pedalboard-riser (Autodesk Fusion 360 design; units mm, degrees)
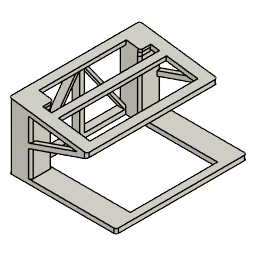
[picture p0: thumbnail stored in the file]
sketch "Sketch1" plane through (0, 0, 0) normal (0, 0, 1) x axis (1, 0, 0)
  line L1 (140.375, 0) -> (0, 0)
  line L2 (140.375, 171.375) -> (140.375, 0)
  line L3 (0, 171.375) -> (140.375, 171.375)
  line L4 (0, 0) -> (0, 171.375)
  point P1 (0, 0)
  point P2 (0, 0)
  point P3 (140.375, 0)
  point P5 (0, 171.375)
  horizontal L1
  vertical L2
  horizontal L3
  vertical L4
  coincident P1 P2
  dimension "d1" distance P2 P3 = 140.375
  dimension "d2" distance P2 P5 = 171.375
extrude "Extrude1" new body sketch "Sketch1" along normal blind 6.15
sketch "Sketch2" plane through (0, 0, 6.15) normal (0, 0, 1) x axis (-1, 0, 0)
  line L1 (0, 0) -> (0, -171.375)
  line L2 (-140.375, 0) -> (0, 0)
  line L3 (-140.375, -171.375) -> (-140.375, 0)
  line L4 (0, -171.375) -> (-140.375, -171.375)
  line L5 (-10, -28.549) -> (-130.375, -28.549)
  line L6 (-10, -142.826) -> (-10, -28.549)
  line L7 (-130.375, -142.826) -> (-10, -142.826)
  line L8 (-130.375, -28.549) -> (-130.375, -142.826)
  line L9 (-10, -85.6875) -> (0, -85.6875)
  line L10 (-130.375, -85.6875) -> (-140.375, -85.6875)
  line L11 (-70.1875, -28.549) -> (-70.1875, 0)
  line L12 (-70.1875, -142.826) -> (-70.1875, -171.375)
  point P10 (0, -85.6875)
  point P11 (-10, -85.6875)
  point P12 (-140.375, -85.6875)
  point P13 (-130.375, -85.6875)
  point P14 (-70.1875, 0)
  point P15 (-70.1875, -28.549)
  point P16 (-70.1875, -171.375)
  point P17 (-70.1875, -142.826)
  horizontal L5
  vertical L6
  horizontal L7
  vertical L8
  midpoint L1 P10
  coincident L6 P11
  perpendicular L6 L9
  midpoint L3 P12
  coincident L8 P13
  perpendicular L8 L10
  equal L9 L10
  midpoint L2 P14
  midpoint L5 P15
  midpoint L4 P16
  midpoint L7 P17
  equal L11 L12
  dimension "d5" distance L2 L5 = 28.549
  dimension "d7" distance L1 L6 = 10
extrude "Extrude2" cut sketch "Sketch2" profile of L5 L6 L7 L8 against normal blind 45
sketch "Sketch3" plane through (0, 0, 6.15) normal (0, 0, 1) x axis (-1, 0, 0)
  line L1 (-10, -142.826) -> (-10, -28.549)
  line L2 (-130.375, -142.826) -> (-10, -142.826)
  line L3 (-130.375, -28.549) -> (-130.375, -142.826)
  line L4 (-10, -28.549) -> (-130.375, -28.549)
  line L5 (0, 0) -> (0, -171.375)
  line L6 (-140.375, 0) -> (0, 0)
  line L7 (-140.375, -171.375) -> (-140.375, 0)
  line L8 (0, -171.375) -> (-140.375, -171.375)
  line L9 (-28.549, 0) -> (0, 0)
  line L10 (-28.549, -28.549) -> (-28.549, 0)
  line L11 (0, -28.549) -> (-28.549, -28.549)
  line L12 (0, 0) -> (0, -28.549)
  line L13 (-140.375, -85.6875) -> (0, -85.6875)
  line L14 (-140.375, -85.6875) -> (0, -85.6875)
  line L15 (0, -142.826) -> (-28.549, -142.826)
  line L16 (0, -171.375) -> (0, -142.826)
  line L17 (-28.549, -171.375) -> (0, -171.375)
  line L18 (-28.549, -142.826) -> (-28.549, -171.375)
  line L19 (-10, -28.549) -> (0, -28.549)
  point P12 (-28.549, -28.549)
  point P1 (0, 0)
  point P10 (0, 0)
  point P14 (0, -85.6875)
  point P15 (-140.375, -85.6875)
  point P20 (0, -171.375)
  point P11 (-28.549, 0)
  point P21 (-28.549, -171.375)
  point P18 (-28.549, -142.826)
  point P13 (0, -28.549)
  point P19 (0, -142.826)
  point P16 (0, -85.6875)
  point P17 (-140.375, -85.6875)
  horizontal L9
  vertical L10
  horizontal L11
  vertical L12
  coincident L4 P12
  coincident P1 P10
  midpoint L5 P14
  midpoint L7 P15
  symmetric P10 L13 P20
  symmetric P11 L13 P21
  symmetric P12 L13 P18
  symmetric P13 L13 P19
  symmetric P14 L13 P16
  symmetric P15 L13 P17
  horizontal L19
  equal L11 L12
extrude "Extrude3" add sketch "Sketch3" profile of L2 L4 L5 L6 L8 L9 L10 L11 L12 L15 L16 L17 L18 L19 along normal blind 80.4
sketch "Sketch4" plane through (0, 0, 0) normal (-1, 0, 0) x axis (0, -1, 0)
  line L1 (0, 0) -> (-171.375, 0)
  line L2 (0, 86.55) -> (0, 0)
  line L3 (-28.549, 86.55) -> (0, 86.55)
  line L4 (-28.549, 6.15) -> (-28.549, 86.55)
  line L5 (-142.826, 6.15) -> (-28.549, 6.15)
  line L6 (-142.826, 86.55) -> (-142.826, 6.15)
  line L7 (-171.375, 86.55) -> (-142.826, 86.55)
  line L8 (-171.375, 0) -> (-171.375, 86.55)
  line L9 (-85.6875, 6.15) -> (-85.6875, 0)
  line L10 (0, 86.55) -> (-171.375, 86.55)
  line L11 (0, 80.4) -> (0, 86.55)
  line L12 (-171.375, 80.4) -> (0, 80.4)
  line L13 (-171.375, 86.55) -> (-171.375, 80.4)
  line L14 (-85.6875, 86.55) -> (-85.6875, 0)
  line L15 (-82.6125, 86.55) -> (-88.7625, 86.55)
  line L16 (-82.6125, 0) -> (-82.6125, 86.55)
  line L17 (-88.7625, 0) -> (-82.6125, 0)
  line L18 (-88.7625, 86.55) -> (-88.7625, 0)
  line L19 (-88.7625, 43.275) -> (-85.6875, 43.275)
  line L20 (-82.6125, 43.275) -> (-85.6875, 43.275)
  line L21 (-142.826, 6.15) -> (-85.6875, 86.55)
  line L22 (-28.549, 6.15) -> (-85.6875, 86.55)
  line L23 (-88.7625, 86.55) -> (-142.826, 10.4769)
  line L24 (-28.549, 10.4769) -> (-82.6125, 86.55)
  line L25 (-88.7625, 80.4) -> (-141.5303, 6.15)
  line L26 (-29.8447, 6.15) -> (-82.6125, 80.4)
  line L27 (-88.7625, 86.55) -> (-88.7625, 80.4)
  line L28 (-82.6125, 86.55) -> (-82.6125, 80.4)
  point P10 (-85.6875, 0)
  point P11 (-85.6875, 6.15)
  point P14 (0, 80.4)
  point P9 (-171.375, 86.55)
  point P12 (-171.375, 86.55)
  point P16 (-85.6875, 86.55)
  point P19 (-82.6125, 0)
  point P17 (-88.7625, 86.55)
  point P21 (-85.6875, 43.275)
  point P22 (-88.7625, 43.275)
  point P23 (-82.6125, 43.275)
  point P7 (-142.826, 6.15)
  point P24 (-142.826, 6.15)
  point P6 (-28.549, 6.15)
  point P25 (-28.549, 6.15)
  point P26 (-142.826, 10.4769)
  point P27 (-28.549, 10.4769)
  point P28 (-141.5303, 6.15)
  point P29 (-88.7625, 80.4)
  point P30 (-82.6125, 80.4)
  point P31 (-29.8447, 6.15)
  midpoint L1 P10
  midpoint L5 P11
  horizontal L10
  vertical L11
  horizontal L12
  vertical L13
  coincident L2 P14
  coincident P9 P12
  equal L9 L13
  midpoint L10 P16
  horizontal L15
  vertical L16
  horizontal L17
  vertical L18
  coincident L1 P19
  coincident L10 P17
  equal L9 L15
  midpoint L14 P21
  midpoint L18 P22
  midpoint L16 P23
  equal L19 L20
  coincident P7 P24
  coincident P6 P25
  coincident L6 P26
  coincident L4 P27
  coincident L5 P28
  coincident L12 P29
  coincident L18 P29
  coincident L16 P30
  coincident L12 P30
  coincident L5 P31
  parallel L21 L23
  parallel L21 L25
  parallel L22 L26
  parallel L22 L24
extrude "Extrude4" add sketch "Sketch4" profile of L4 L5 L6 L10 L12 L15 L16 L18 L23 L24 L25 L26 L27 L28 against normal blind 10
sketch "Sketch5" plane through (0, 0, 0) normal (0, -1, 0) x axis (1, 0, 0)
  line L1 (140.375, 0) -> (0, 0)
  line L2 (140.375, 6.15) -> (140.375, 0)
  line L3 (28.549, 6.15) -> (140.375, 6.15)
  line L4 (28.549, 86.55) -> (28.549, 6.15)
  line L5 (0, 86.55) -> (28.549, 86.55)
  line L6 (0, 0) -> (0, 86.55)
  line L7 (101.825, 72.75) -> (0, 86.55)
  line L8 (101.825, 66.75) -> (101.825, 72.75)
  line L9 (0, 80.55) -> (101.825, 66.75)
  line L10 (0, 86.55) -> (0, 80.55)
  line L11 (101.825, 6.15) -> (101.825, 66.75)
  line L12 (140.375, 6.15) -> (101.825, 66.75)
  line L13 (101.825, 6.15) -> (140.375, 6.15)
  point P12 (101.825, 6.15)
  point P4 (140.375, 6.15)
  point P13 (140.375, 6.15)
  point P7 (0, 86.55)
  point P8 (0, 86.55)
  point P10 (101.825, 66.75)
  point P9 (101.825, 72.75)
  perpendicular L5 L8
  parallel L7 L9
  perpendicular L5 L10
  coincident L3 P12
  perpendicular L3 L11
  coincident P4 P13
  collinear L6 L10
  coincident P7 P8
  dimension "d17" distance P10 P13 = 71.8224
  dimension "d18" distance P12 P13 = 38.55
  dimension "d19" distance P10 P12 = 60.6
  dimension "d20" distance P9 P10 = 6
extrude "Extrude5" add sketch "Sketch5" profile of L4 L6 L7 L8 L9 L10 against normal blind 171.375
sketch "Sketch6" plane through (11.5183, 0, 84.989) normal (0.1343, 0, 0.9909) x axis (0, 1, 0)
  line L1 (142.826, -17.1864) -> (171.375, -17.1864)
  line L2 (142.826, 1.5321) -> (142.826, -17.1864)
  line L3 (28.549, 1.5321) -> (142.826, 1.5321)
  line L4 (28.549, -17.1864) -> (28.549, 1.5321)
  line L5 (0, -17.1864) -> (28.549, -17.1864)
  line L6 (0, -91.1323) -> (0, -17.1864)
  line L7 (171.375, -91.1323) -> (0, -91.1323)
  line L8 (171.375, -17.1864) -> (171.375, -91.1323)
  line L9 (201.9473, 33.5708) -> (-21.6839, 33.5708)
  line L10 (201.9473, -138.0714) -> (201.9473, 33.5708)
  line L11 (-21.6839, -138.0714) -> (201.9473, -138.0714)
  line L12 (-21.6839, 33.5708) -> (-21.6839, -138.0714)
  horizontal L9
  vertical L10
  horizontal L11
  vertical L12
extrude "Extrude6" cut sketch "Sketch6" along normal blind 70
sketch "Sketch7" plane through (0, 0, 0) normal (0, -1, 0) x axis (1, 0, 0)
  line L1 (0, 86.55) -> (101.825, 72.75)
  line L2 (0, 0) -> (0, 86.55)
  line L3 (140.375, 0) -> (0, 0)
  line L4 (140.375, 6.15) -> (140.375, 0)
  line L5 (28.549, 6.15) -> (140.375, 6.15)
  line L6 (28.549, 76.6808) -> (28.549, 6.15)
  line L7 (101.825, 66.75) -> (28.549, 76.6808)
  line L8 (101.825, 72.75) -> (101.825, 66.75)
  line L9 (28.549, 41.4154) -> (101.825, 66.75)
  line L10 (28.549, 47.7639) -> (88.6338, 68.5378)
  point P9 (101.825, 66.75)
  point P10 (101.825, 66.75)
  point P11 (28.549, 41.4154)
  point P12 (88.6338, 68.5378)
  point P13 (28.549, 47.7639)
  coincident P9 P10
  midpoint L6 P11
  coincident L7 P12
  coincident L6 P13
  parallel L9 L10
  dimension "d25" distance L9 L10 = 6
extrude "Extrude7" add sketch "Sketch7" profile of L6 L7 L9 L10 against normal blind 6
sketch "Sketch8" plane through (0, 171.375, 0) normal (0, 1, 0) x axis (-1, 0, 0)
  line L1 (-101.825, 72.75) -> (0, 86.55)
  line L2 (-101.825, 66.75) -> (-101.825, 72.75)
  line L3 (-28.549, 76.6808) -> (-101.825, 66.75)
  line L4 (-28.549, 6.15) -> (-28.549, 76.6808)
  line L5 (-140.375, 6.15) -> (-28.549, 6.15)
  line L6 (-140.375, 0) -> (-140.375, 6.15)
  line L7 (0, 0) -> (-140.375, 0)
  line L8 (0, 86.55) -> (0, 0)
  line L9 (-101.825, 66.75) -> (-88.6338, 68.5378)
  line L10 (-28.549, 41.4154) -> (-101.825, 66.75)
  line L11 (-28.549, 47.7639) -> (-28.549, 41.4154)
  line L12 (-88.6338, 68.5378) -> (-28.549, 47.7639)
extrude "Extrude8" add sketch "Sketch8" profile of L3 L4 L9 L10 L11 L12 against normal blind 6
fillet "Fillet1" radius 3
fillet "Fillet2" radius 3
sketch "Sketch9" plane through (11.5183, 0, 84.989) normal (0.1343, 0, 0.9909) x axis (0, 1, 0)
  line L1 (168.375, -91.1323) -> (3, -91.1323)
  line L2 (171.375, 8.5961) -> (171.375, -88.1049)
  line L3 (3, 11.6236) -> (168.375, 11.6236)
  line L4 (0, -88.1049) -> (0, 8.5961)
  line L5 (156.375, -38.8323) -> (15, -38.8323)
  line L6 (156.375, -80.1323) -> (156.375, -38.8323)
  line L7 (15, -80.1323) -> (156.375, -80.1323)
  line L8 (15, -38.8323) -> (15, -80.1323)
  line L9 (156.375, -29.3764) -> (15, -29.3764)
  line L10 (156.375, 0.6236) -> (156.375, -29.3764)
  line L11 (15, 0.6236) -> (156.375, 0.6236)
  line L12 (15, -29.3764) -> (15, 0.6236)
  line L13 (171.375, -39.7544) -> (0, -39.7544)
  line L14 (0, -14.3764) -> (15, -14.3764)
  line L15 (171.375, -14.3764) -> (156.375, -14.3764)
  line L16 (85.6875, 0.6236) -> (85.6875, 11.6236)
  line L17 (85.6875, -80.1323) -> (85.6875, -91.1323)
  line L18 (0, -59.4823) -> (15, -59.4823)
  line L19 (171.375, -59.4823) -> (156.375, -59.4823)
  closed curve K1 centre (3, -88.1049)
  closed curve K2 centre (168.375, -88.1049)
  closed curve K3 centre (168.375, 8.5961)
  closed curve K4 centre (3, 8.5961)
  point P22 (0, -39.7544)
  point P23 (171.375, -39.7544)
  point P24 (15, -14.3764)
  point P25 (0, -14.3764)
  point P26 (156.375, -14.3764)
  point P27 (171.375, -14.3764)
  point P28 (85.6875, 11.6236)
  point P29 (85.6875, 0.6236)
  point P30 (85.6875, -91.1323)
  point P31 (85.6875, -80.1323)
  point P32 (15, -59.4823)
  point P33 (0, -59.4823)
  point P34 (156.375, -59.4823)
  point P35 (171.375, -59.4823)
  point P14 (15, -38.8323)
  point P17 (15, -80.1323)
  point P18 (15, -29.3764)
  point P21 (15, 0.6236)
  horizontal L5
  vertical L6
  horizontal L7
  vertical L8
  horizontal L9
  vertical L10
  horizontal L11
  vertical L12
  collinear L8 L12
  collinear L6 L10
  midpoint L4 P22
  midpoint L2 P23
  midpoint L12 P24
  coincident L4 P25
  perpendicular L4 L14
  midpoint L10 P26
  coincident L2 P27
  perpendicular L2 L15
  midpoint L3 P28
  midpoint L11 P29
  midpoint L1 P30
  midpoint L7 P31
  midpoint L8 P32
  coincident L4 P33
  perpendicular L4 L18
  midpoint L6 P34
  coincident L2 P35
  perpendicular L2 L19
  dimension "d34" distance L1 L7 = 11
  dimension "d36" distance P14 P17 = 41.3
  dimension "d37" distance L4 L8 = 15
  dimension "d38" distance L2 L6 = 15
  dimension "d39" distance P18 P21 = 30
  dimension "d40" distance L3 L11 = 11
extrude "Extrude9" cut sketch "Sketch9" profile of L5 L6 L7 L8 L9 L10 L11 L12 against normal blind 6
extrude "Extrude10" add of existing geometry blind 6
fillet "Fillet3" radius 35
fillet "Fillet4" radius 3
